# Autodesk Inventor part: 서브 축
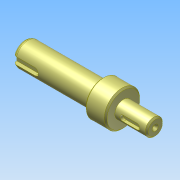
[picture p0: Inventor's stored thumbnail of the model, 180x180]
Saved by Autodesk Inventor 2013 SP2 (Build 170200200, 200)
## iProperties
Created: 2026-07
Part Number: 서브 축
Material: Generic
Document SubType Name: Modeling
Designer: a
Density: 1 g/cm^3
Author: a
변환 표준: STEP AP214IS
전처리기: Build: 200, Release: 2013 SP2 Update 6 - Date: Thu 07/17/2014
전송 단위: 밀리미터
불확실성: 0.01
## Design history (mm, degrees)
node "서브 축1"
node "솔리드1"
node "기준1"
